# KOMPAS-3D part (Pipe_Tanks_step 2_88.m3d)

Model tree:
1. X Axis
2. Y Axis
3. Z Axis  (labels: Pipe Dn 50; Valve Dy 50)
     Òîëùèíà ñòåíêè 1 = 1

Referenced files in C:\Documents and Settings\kashirsky\Мои документы\Camtasia Studio\Pipelines3D\Tanks\: Tanks_step 4.a3d
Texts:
  Pipe Dn 50
  Steel ASTM A295
  Three Point Plane
  Plane at Angle
  Line and Point Plane
  Axis through Two Vertices
  Axis of Feature
  Axis of Conical Surface
  Axis through Edge
  Trim by Surface
  Trim by Sketch
  Feature with No History
  Intersection Axis of Two Planes
  Two Line Plane
  Line and Face Plane
  Bend by line
  Hole in sheet body
  Cut in sheet body
  Point in CM
  Linear Dimension from Line to Point
  Surface Finish Symbol
  Geometric Tolerance Symbol
  Leader #1
  Leader #2
  Leader #3
  Shape Deviations and Datum
  Node point number
  Mark of coordination axis
  Node point designation
  Mark/Reference designation with leader
  Mark/reference designation on line
  Mark/Reference designation without leader
  Valve Dy 50
  Plane of section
